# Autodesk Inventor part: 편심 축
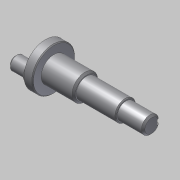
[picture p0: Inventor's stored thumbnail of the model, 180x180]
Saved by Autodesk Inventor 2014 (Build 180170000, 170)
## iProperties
Created: 2015-10
Part Number: 편심 축
Document SubType Name: Modeling
Designer: mdu
Density: 7.86 g/cm^3
Material: 강철, 연강
Mass: 78.4913 g
Surface Area: 37.9919 cm^2
Volume: 9.98617 cm^3
Appearance: 기본값
Author: mdu
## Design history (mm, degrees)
sketch "스케치1"
  geometry: L1 (1.75, -12.001)-(1.75, 11.999) reference; L2 (-16.95, -14)-(-16.95, 14) reference; L3 (-36.25, -18.06)-(-36.25, 18.06) reference; L4 (-41.25, 0)-(20.75, 0); L5 (-41.25, 0)-(-41.25, 12.5); L6 (-41.25, 12.5)-(-36.25, 12.5); L7 (-36.25, 12.5)-(-36.25, 7.5); L8 (-36.25, 7.5)-(-17.25, 7.5); L9 (-17.25, 6)-(5.75, 6); L10 (20.75, 5)-(20.75, 0); L11 (5.75, 6)-(5.75, 5); L12 (5.75, 5)-(20.75, 5); L13 (-17.25, -13.7)-(-17.25, 13.7) reference; L14 (-17.25, 7.5)-(-17.25, 6); 2 further points
  constraints: 20 end point, 7 perpendicular, 5 point on line, 1 collinear, 1 midpoint, 1 parallel
  dimensions: "d0" = 12 diameter of L9 L4; "d1" = 15 diameter of L8 L4; "d2" = 25 diameter of L6 L4; "d3" = 5 distance of L5.end L6.end; "d4" = 62 distance of L4.start L4.end; "d5" = 10 diameter of L12 L4; "d6" = 15 distance of L11.end L10.start
revolve "회전1" sketch "스케치1" stored, may be unused: angle "d7" = 90 deg
sketch "스케치2"
  geometry: C1 r 4 at (0, -7.5); C2 r 5 at (0, -7.5); C3 r 12.5 at (0, 0) reference; 1 further point
  constraints: 2 centre point, 1 coincident, 1 tangent, 1 vertical alignment
  dimensions: "d8" = 8 diameter of C1; "d9" = 7.5 distance of point (0, 0) C1.centre
extrude "돌출1" join sketch "스케치2" distance "d10" = 10; taper "d11" = 0 deg
extrude "돌출2" join sketch "스케치2" distance "d12" = 0.5; taper "d13" = 0 deg
node "작업 평면1"
sketch "스케치3"
  geometry: L1 (-7.5, 5)-(-7.5, -5) reference; L2 (-7.5, 1.5)-(3, 1.5); L3 (3, -1.5)-(-7.5, -1.5); A1 r 1.5 centre (3, 0) between (3, -1.5) and (3, 1.5); 2 further points
  constraints: 4 end point, 2 perpendicular, 2 point on circle, 2 point on line, 2 tangent, 1 centre point, 1 horizontal alignment, 1 midpoint
  dimensions: "d14" = 3 distance between parallel lines of L3 L2; "d15" = 12 dimension on A1 L1
extrude "돌출3" cut sketch "스케치3" distance "d16" = 1.8; taper "d17" = 0 deg
chamfer "모따기1" distance "d18" = 1; stored, may be unused: second distance "d19" = 2, angle "d20" = 45 deg
chamfer "모따기2" distance "d21" = 0.5; stored, may be unused: second distance "d22" = 2, angle "d23" = 45 deg
node "솔리드1"
node "참조1"
node "참조2"
node "참조3"
node "참조4"
